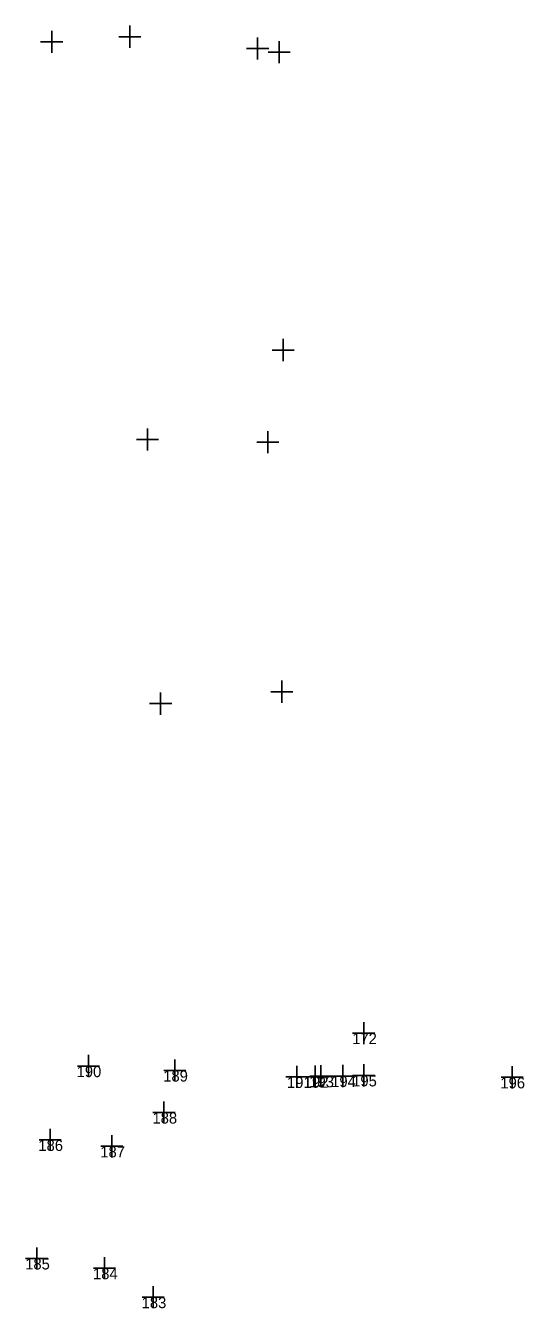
# Model space of a CAD drawing. Extents: x -706655 to -706193, y -1036183 to -1034979.
# Drawn here: x -706410.4 to -706387.9, y -1035888 to -1035830 of the extents above; entities that cross this region are included whole.
import ezdxf

# ---------------------------------------------------------------- set-up
doc = ezdxf.new("R2010")
doc.units = 0
doc.layers.add('čísla bodu', color=7, linetype='Continuous')

msp = doc.modelspace()

# ---------------------------------------------------------------- linework, layer by layer
at = {"layer": 'čísla bodu'}
for p, q in [((-706409.25, -1035831.24), (-706409.25, -1035830.24)), ((-706409.25, -1035831.24), (-706409.25, -1035830.24)), ((-706405.71, -1035831.01), (-706405.71, -1035830.01)), ((-706405.71, -1035831.01), (-706405.71, -1035830.01)), ((-706409.75, -1035830.74), (-706408.75, -1035830.74)), ((-706409.75, -1035830.74), (-706408.75, -1035830.74)), ((-706409.25, -1035830.74), (-706409.25, -1035830.74)), ((-706409.25, -1035830.74), (-706409.25, -1035830.74)), ((-706406.21, -1035830.51), (-706405.21, -1035830.51)), ((-706406.21, -1035830.51), (-706405.21, -1035830.51)), ((-706405.71, -1035830.51), (-706405.71, -1035830.51)), ((-706405.71, -1035830.51), (-706405.71, -1035830.51)), ((-706399.93, -1035831.54), (-706399.93, -1035830.54)), ((-706399.93, -1035831.54), (-706399.93, -1035830.54)), ((-706398.96, -1035831.71), (-706398.96, -1035830.71)), ((-706398.96, -1035831.71), (-706398.96, -1035830.71)), ((-706400.43, -1035831.04), (-706399.43, -1035831.04)), ((-706400.43, -1035831.04), (-706399.43, -1035831.04)), ((-706399.93, -1035831.04), (-706399.93, -1035831.04)), ((-706399.93, -1035831.04), (-706399.93, -1035831.04)), ((-706399.46, -1035831.21), (-706398.46, -1035831.21)), ((-706399.46, -1035831.21), (-706398.46, -1035831.21)), ((-706398.96, -1035831.21), (-706398.96, -1035831.21)), ((-706398.96, -1035831.21), (-706398.96, -1035831.21)), ((-706398.78, -1035845.18), (-706398.78, -1035844.18)), ((-706398.78, -1035845.18), (-706398.78, -1035844.18)), ((-706399.28, -1035844.68), (-706398.28, -1035844.68)), ((-706399.28, -1035844.68), (-706398.28, -1035844.68)), ((-706398.78, -1035844.68), (-706398.78, -1035844.68)), ((-706398.78, -1035844.68), (-706398.78, -1035844.68)), ((-706404.91, -1035849.23), (-706404.91, -1035848.23)), ((-706404.91, -1035849.23), (-706404.91, -1035848.23)), ((-706399.47, -1035849.35), (-706399.47, -1035848.35)), ((-706399.47, -1035849.35), (-706399.47, -1035848.35)), ((-706405.41, -1035848.73), (-706404.41, -1035848.73)), ((-706405.41, -1035848.73), (-706404.41, -1035848.73)), ((-706404.91, -1035848.73), (-706404.91, -1035848.73)), ((-706404.91, -1035848.73), (-706404.91, -1035848.73)), ((-706399.97, -1035848.85), (-706398.97, -1035848.85)), ((-706399.97, -1035848.85), (-706398.97, -1035848.85)), ((-706399.47, -1035848.85), (-706399.47, -1035848.85)), ((-706399.47, -1035848.85), (-706399.47, -1035848.85)), ((-706398.83, -1035860.63), (-706398.83, -1035859.63)), ((-706398.83, -1035860.63), (-706398.83, -1035859.63)), ((-706404.32, -1035861.17), (-706404.32, -1035860.17)), ((-706404.32, -1035861.17), (-706404.32, -1035860.17)), ((-706399.33, -1035860.13), (-706398.33, -1035860.13)), ((-706399.33, -1035860.13), (-706398.33, -1035860.13)), ((-706398.83, -1035860.13), (-706398.83, -1035860.13)), ((-706398.83, -1035860.13), (-706398.83, -1035860.13)), ((-706404.82, -1035860.67), (-706403.82, -1035860.67)), ((-706404.82, -1035860.67), (-706403.82, -1035860.67)), ((-706404.32, -1035860.67), (-706404.32, -1035860.67)), ((-706404.32, -1035860.67), (-706404.32, -1035860.67)), ((-706395.13, -1035876.07), (-706395.13, -1035875.07)), ((-706395.63, -1035875.57), (-706394.63, -1035875.57)), ((-706395.13, -1035875.57), (-706395.13, -1035875.57)), ((-706407.58, -1035877.56), (-706407.58, -1035876.56)), ((-706403.68, -1035877.76), (-706403.68, -1035876.76)), ((-706408.08, -1035877.06), (-706407.08, -1035877.06)), ((-706407.58, -1035877.06), (-706407.58, -1035877.06)), ((-706404.18, -1035877.26), (-706403.18, -1035877.26)), ((-706403.68, -1035877.26), (-706403.68, -1035877.26)), ((-706398.15, -1035878.05), (-706398.15, -1035877.05)), ((-706397.32, -1035878.04), (-706397.32, -1035877.04)), ((-706397.07, -1035878.02), (-706397.07, -1035877.02)), ((-706396.08, -1035878.01), (-706396.08, -1035877.01)), ((-706395.13, -1035877.98), (-706395.13, -1035876.98)), ((-706388.41, -1035878.07), (-706388.41, -1035877.07)), ((-706398.65, -1035877.55), (-706397.65, -1035877.55)), ((-706398.15, -1035877.55), (-706398.15, -1035877.55)), ((-706397.82, -1035877.54), (-706396.82, -1035877.54)), ((-706397.57, -1035877.52), (-706396.57, -1035877.52)), ((-706397.32, -1035877.54), (-706397.32, -1035877.54)), ((-706397.07, -1035877.52), (-706397.07, -1035877.52)), ((-706396.58, -1035877.51), (-706395.58, -1035877.51)), ((-706396.08, -1035877.51), (-706396.08, -1035877.51)), ((-706395.63, -1035877.48), (-706394.63, -1035877.48)), ((-706395.13, -1035877.48), (-706395.13, -1035877.48)), ((-706388.91, -1035877.57), (-706387.91, -1035877.57)), ((-706388.41, -1035877.57), (-706388.41, -1035877.57)), ((-706404.17, -1035879.66), (-706404.17, -1035878.66)), ((-706404.67, -1035879.16), (-706403.67, -1035879.16)), ((-706404.17, -1035879.16), (-706404.17, -1035879.16)), ((-706409.32, -1035880.9), (-706409.32, -1035879.9)), ((-706406.53, -1035881.19), (-706406.53, -1035880.19)), ((-706409.82, -1035880.4), (-706408.82, -1035880.4)), ((-706409.32, -1035880.4), (-706409.32, -1035880.4)), ((-706407.03, -1035880.69), (-706406.03, -1035880.69)), ((-706406.53, -1035880.69), (-706406.53, -1035880.69)), ((-706409.93, -1035886.26), (-706409.93, -1035885.26)), ((-706410.43, -1035885.76), (-706409.43, -1035885.76)), ((-706409.93, -1035885.76), (-706409.93, -1035885.76)), ((-706406.86, -1035886.7), (-706406.86, -1035885.7)), ((-706407.36, -1035886.2), (-706406.36, -1035886.2)), ((-706406.86, -1035886.2), (-706406.86, -1035886.2)), ((-706404.66, -1035888.01), (-706404.66, -1035887.01)), ((-706405.16, -1035887.51), (-706404.16, -1035887.51)), ((-706404.66, -1035887.51), (-706404.66, -1035887.51))]:
    msp.add_line(p, q, dxfattribs=at)

# ---------------------------------------------------------------- texts
for s, p in [('172', (-706395.65, -1035876.07)), ('190', (-706408.123, -1035877.56)), ('189', (-706404.202, -1035877.76)), ('191', (-706398.602, -1035878.05)), ('192', (-706397.842, -1035878.04)), ('193', (-706397.592, -1035878.02)), ('194', (-706396.602, -1035878.01)), ('195', (-706395.652, -1035877.98)), ('196', (-706388.945, -1035878.07)), ('188', (-706404.69, -1035879.66)), ('186', (-706409.854, -1035880.9)), ('187', (-706407.05, -1035881.19)), ('185', (-706410.45, -1035886.26)), ('184', (-706407.38, -1035886.7)), ('183', (-706405.18, -1035888.01))]:
    msp.add_text(s, height=0.5, dxfattribs=at).set_placement(p)

doc.saveas('drawing.dxf')
